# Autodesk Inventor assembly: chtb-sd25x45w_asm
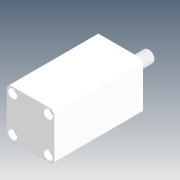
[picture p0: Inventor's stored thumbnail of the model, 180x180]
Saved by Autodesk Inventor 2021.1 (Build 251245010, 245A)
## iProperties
Company: Microsoft
Created: 2018-05
Part Number: chtb-sd25x45w_asm
Description: STEP AP214
Document SubType Name: Assembly
Designer: user
Title: chtb-sd25x45w_asm.STEP
Author: Windows
Revision Number: ÈÎºÎ
Sending System: SolidWorks 2015
Preprocessor: SwSTEP 2.0
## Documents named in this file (4)
- D:\Vault_2016\Projekty\Clamptek\Hydraulic\CHTB\CHTB-25\Inventor\chtb-sd25x45w\chtb-sd25x45w_asm.iam
- D:\Vault_2016\Projekty\Clamptek\Hydraulic\CHTB\CHTB-25\Inventor\chtb-sd25x45w\CHTB-25QG.ipt
- D:\Vault_2016\Projekty\Clamptek\Hydraulic\CHTB\CHTB-25\Inventor\chtb-sd25x45w\CHTB-SD25X45NBT.ipt
- D:\Vault_2016\Projekty\Clamptek\Hydraulic\CHTB\CHTB-25\Inventor\chtb-sd25x45w\CHTB-SD25X45WHSG.ipt
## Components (3 placed, 3 different names)
1. CHTB-25QG_1
2. CHTB-SD25X45NBT_2
3. CHTB-SD25X45WHSG_3
